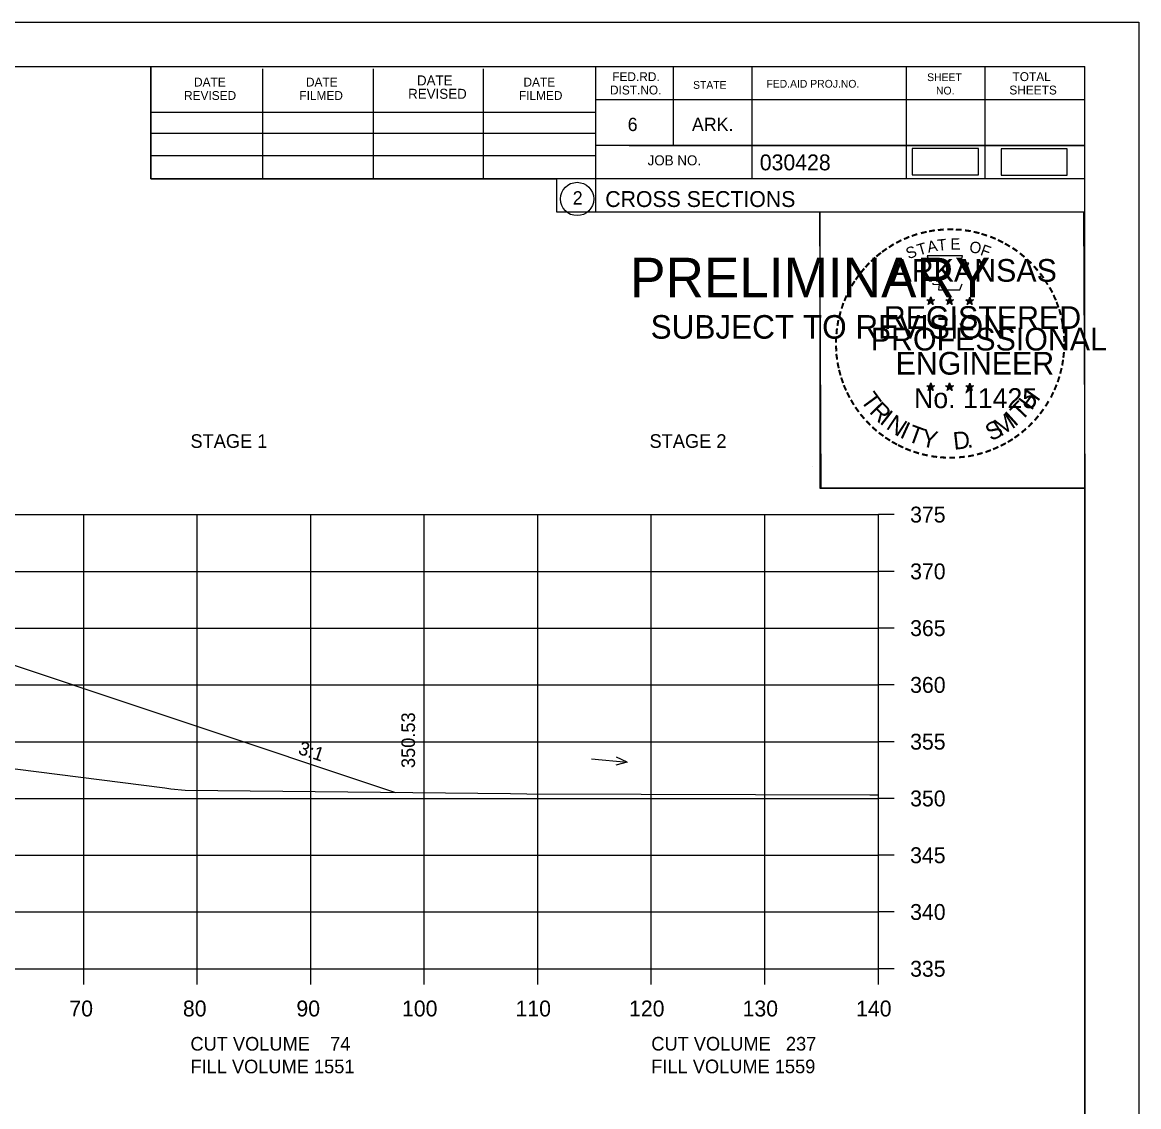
# Model space of a CAD drawing. Extents: x 1374859 to 1376773, y 382242 to 389804.
# Drawn here: x 1376199.2 to 1376297.5, y 384279.6 to 384375.1 of the extents above; entities that cross this region are included whole.
import ezdxf

# ---------------------------------------------------------------- set-up
doc = ezdxf.new("R2010")
doc.units = 0
for name, color, linetype in [('R_Axis', 7, 'Continuous'), ('R_Axis Annot', 7, 'Continuous'), ('R_Border', 7, 'Continuous'), ('R_Border PE', 7, 'Continuous'), ('R_Border Prem', 7, 'Continuous'), ('R_Exist Surface', 7, 'Continuous'), ('R_Fin Surface', 7, 'Continuous'), ('R_Grid', 7, 'Continuous'), ('R_MOT', 7, 'Continuous'), ('R_No Plot', 7, 'Continuous'), ('R_Water Annot', 7, 'Continuous'), ('R_Xsect Elev', 7, 'Continuous'), ('R_Xsect Slope', 7, 'Continuous')]:
    doc.layers.add(name, color=color, linetype=linetype)

msp = doc.modelspace()

# ---------------------------------------------------------------- linework, layer by layer
at = {"layer": 'R_Axis'}
for p, q in [((1376274.57, 384291.762), (1376274.57, 384331.762)), ((1376275.97, 384331.762), (1376274.57, 384331.762)), ((1376275.97, 384326.762), (1376274.57, 384326.762)), ((1376275.97, 384321.762), (1376274.57, 384321.762)), ((1376275.97, 384316.762), (1376274.57, 384316.762)), ((1376275.97, 384311.762), (1376274.57, 384311.762)), ((1376275.97, 384306.762), (1376274.57, 384306.762)), ((1376275.97, 384301.762), (1376274.57, 384301.762)), ((1376275.97, 384296.762), (1376274.57, 384296.762)), ((1375994.57, 384291.762), (1376274.57, 384291.762)), ((1376204.57, 384290.362), (1376204.57, 384291.762)), ((1376214.57, 384290.362), (1376214.57, 384291.762)), ((1376224.57, 384290.362), (1376224.57, 384291.762)), ((1376234.57, 384290.362), (1376234.57, 384291.762)), ((1376244.57, 384290.362), (1376244.57, 384291.762)), ((1376254.57, 384290.362), (1376254.57, 384291.762)), ((1376264.57, 384290.362), (1376264.57, 384291.762)), ((1376274.57, 384290.362), (1376274.57, 384291.762)), ((1376275.97, 384291.762), (1376274.57, 384291.762))]:
    msp.add_line(p, q, dxfattribs=at)
at = {"layer": 'R_Border'}
for p, q in [((1375976.57, 384371.222), (1376292.75, 384371.222)), ((1376210.49, 384361.342), (1376210.49, 384371.222)), ((1376220.35, 384361.342), (1376220.35, 384371.022)), ((1376230.11, 384361.342), (1376230.11, 384371.022)), ((1376239.79, 384361.342), (1376239.79, 384371.022)), ((1376249.65, 384371.222), (1376249.65, 384358.422)), ((1376256.49, 384371.222), (1376256.49, 384364.282)), ((1376263.43, 384371.222), (1376263.43, 384361.342)), ((1376277.01, 384371.222), (1376277.01, 384361.342)), ((1376283.95, 384371.222), (1376283.95, 384361.342)), ((1376292.75, 384165.762), (1376292.75, 384371.222)), ((1376292.75, 384368.282), (1376249.65, 384368.282)), ((1376292.75, 384368.302), (1376292.75, 384368.302)), ((1376210.49, 384367.202), (1376249.65, 384367.202)), ((1376210.49, 384365.342), (1376249.65, 384365.342)), ((1376292.75, 384364.282), (1376249.65, 384364.282)), ((1376252.61, 384364.282), (1376292.75, 384364.282)), ((1376210.49, 384361.342), (1376210.49, 384363.402)), ((1376210.49, 384363.402), (1376249.65, 384363.402)), ((1376292.75, 384361.342), (1376210.49, 384361.342)), ((1376249.65, 384358.422), (1376292.75, 384358.422))]:
    msp.add_line(p, q, dxfattribs=at)
msp.add_circle((1376248.037, 384359.558), 1.467, dxfattribs=at)
at = {"layer": 'R_Border PE'}
for p, q in [((1376278.835, 384350.677), (1376279.184, 384350.566)), ((1376278.835, 384350.677), (1376279.088, 384350.632)), ((1376278.835, 384350.677), (1376279.072, 384350.555)), ((1376278.968, 384350.269), (1376279.184, 384350.566)), ((1376278.968, 384350.269), (1376279.094, 384350.513)), ((1376278.968, 384350.269), (1376279.182, 384350.486)), ((1376279.184, 384350.931), (1376279.143, 384350.679)), ((1376279.397, 384350.269), (1376279.182, 384350.483)), ((1376279.184, 384350.566), (1376279.184, 384350.931)), ((1376279.184, 384350.931), (1376279.233, 384350.681)), ((1376279.531, 384350.677), (1376279.184, 384350.566)), ((1376279.397, 384350.269), (1376279.184, 384350.566)), ((1376279.531, 384350.677), (1376279.245, 384350.628)), ((1376279.397, 384350.269), (1376279.26, 384350.56)), ((1376279.531, 384350.677), (1376279.327, 384350.575)), ((1376280.505, 384350.677), (1376280.854, 384350.566)), ((1376280.505, 384350.677), (1376280.758, 384350.632)), ((1376280.505, 384350.677), (1376280.742, 384350.555)), ((1376280.638, 384350.269), (1376280.854, 384350.566)), ((1376280.638, 384350.269), (1376280.764, 384350.513)), ((1376280.638, 384350.269), (1376280.852, 384350.486)), ((1376280.854, 384350.931), (1376280.813, 384350.679)), ((1376281.067, 384350.269), (1376280.852, 384350.483)), ((1376280.854, 384350.566), (1376280.854, 384350.931)), ((1376280.854, 384350.931), (1376280.903, 384350.681)), ((1376281.201, 384350.677), (1376280.854, 384350.566)), ((1376281.067, 384350.269), (1376280.854, 384350.566)), ((1376281.201, 384350.677), (1376280.915, 384350.628)), ((1376281.067, 384350.269), (1376280.93, 384350.56)), ((1376281.201, 384350.677), (1376280.997, 384350.575)), ((1376282.269, 384350.665), (1376282.618, 384350.554)), ((1376282.269, 384350.665), (1376282.522, 384350.62)), ((1376282.269, 384350.665), (1376282.506, 384350.543)), ((1376282.402, 384350.257), (1376282.618, 384350.554)), ((1376282.402, 384350.257), (1376282.528, 384350.501)), ((1376282.402, 384350.257), (1376282.616, 384350.474)), ((1376282.618, 384350.919), (1376282.577, 384350.667)), ((1376282.831, 384350.257), (1376282.616, 384350.471)), ((1376282.618, 384350.554), (1376282.618, 384350.919)), ((1376282.618, 384350.919), (1376282.667, 384350.669)), ((1376282.965, 384350.665), (1376282.618, 384350.554)), ((1376282.831, 384350.257), (1376282.618, 384350.554)), ((1376282.965, 384350.665), (1376282.679, 384350.616)), ((1376282.831, 384350.257), (1376282.694, 384350.548)), ((1376282.965, 384350.665), (1376282.761, 384350.563)), ((1376279.18, 384343.358), (1376279.139, 384343.106)), ((1376279.18, 384342.993), (1376279.18, 384343.358)), ((1376279.18, 384343.358), (1376279.229, 384343.108)), ((1376280.849, 384343.358), (1376280.808, 384343.106)), ((1376280.849, 384342.993), (1376280.849, 384343.358)), ((1376280.849, 384343.358), (1376280.898, 384343.108)), ((1376282.616, 384343.348), (1376282.575, 384343.096)), ((1376282.616, 384342.983), (1376282.616, 384343.348)), ((1376282.616, 384343.348), (1376282.665, 384343.098)), ((1376278.831, 384343.104), (1376279.18, 384342.993)), ((1376278.831, 384343.104), (1376279.084, 384343.059)), ((1376278.831, 384343.104), (1376279.068, 384342.982)), ((1376278.964, 384342.696), (1376279.18, 384342.993)), ((1376278.964, 384342.696), (1376279.09, 384342.94)), ((1376278.964, 384342.696), (1376279.178, 384342.913)), ((1376279.393, 384342.696), (1376279.178, 384342.91)), ((1376279.527, 384343.104), (1376279.18, 384342.993)), ((1376279.393, 384342.696), (1376279.18, 384342.993)), ((1376279.527, 384343.104), (1376279.241, 384343.055)), ((1376279.393, 384342.696), (1376279.256, 384342.987)), ((1376279.527, 384343.104), (1376279.323, 384343.002)), ((1376280.5, 384343.104), (1376280.849, 384342.993)), ((1376280.5, 384343.104), (1376280.753, 384343.059)), ((1376280.5, 384343.104), (1376280.737, 384342.982)), ((1376280.633, 384342.696), (1376280.849, 384342.993)), ((1376280.633, 384342.696), (1376280.759, 384342.94)), ((1376280.633, 384342.696), (1376280.847, 384342.913)), ((1376281.062, 384342.696), (1376280.847, 384342.91)), ((1376281.196, 384343.104), (1376280.849, 384342.993)), ((1376281.062, 384342.696), (1376280.849, 384342.993)), ((1376281.196, 384343.104), (1376280.91, 384343.055)), ((1376281.062, 384342.696), (1376280.925, 384342.987)), ((1376281.196, 384343.104), (1376280.992, 384343.002)), ((1376282.267, 384343.094), (1376282.616, 384342.983)), ((1376282.267, 384343.094), (1376282.52, 384343.049)), ((1376282.267, 384343.094), (1376282.504, 384342.972)), ((1376282.4, 384342.686), (1376282.616, 384342.983)), ((1376282.4, 384342.686), (1376282.526, 384342.93)), ((1376282.4, 384342.686), (1376282.614, 384342.903)), ((1376282.829, 384342.686), (1376282.614, 384342.9)), ((1376282.963, 384343.094), (1376282.616, 384342.983)), ((1376282.829, 384342.686), (1376282.616, 384342.983)), ((1376282.963, 384343.094), (1376282.677, 384343.045)), ((1376282.829, 384342.686), (1376282.692, 384342.977)), ((1376282.963, 384343.094), (1376282.759, 384342.992))]:
    msp.add_line(p, q, dxfattribs=at)
for points in [[(1376278.876, 384354.555), (1376279.145, 384353.728)], [(1376282.387, 384353.633), (1376282.529, 384353.917), (1376281.844, 384353.893), (1376281.992, 384354.555), (1376278.876, 384354.555)], [(1376279.368, 384352.132), (1376279.368, 384352.045), (1376279.931, 384352.026), (1376279.877, 384351.553), (1376281.747, 384351.553), (1376281.948, 384352.089)], [(1376279.184, 384350.931), (1376279.397, 384350.269), (1376278.835, 384350.677), (1376279.531, 384350.677), (1376278.968, 384350.269), (1376279.184, 384350.931)], [(1376280.854, 384350.931), (1376281.067, 384350.269), (1376280.505, 384350.677), (1376281.201, 384350.677), (1376280.638, 384350.269), (1376280.854, 384350.931)], [(1376282.618, 384350.919), (1376282.831, 384350.257), (1376282.269, 384350.665), (1376282.965, 384350.665), (1376282.402, 384350.257), (1376282.618, 384350.919)], [(1376279.18, 384343.358), (1376279.393, 384342.696), (1376278.831, 384343.104), (1376279.527, 384343.104), (1376278.964, 384342.696), (1376279.18, 384343.358)], [(1376280.849, 384343.358), (1376281.062, 384342.696), (1376280.5, 384343.104), (1376281.196, 384343.104), (1376280.633, 384342.696), (1376280.849, 384343.358)], [(1376282.616, 384343.348), (1376282.829, 384342.686), (1376282.267, 384343.094), (1376282.963, 384343.094), (1376282.4, 384342.686), (1376282.616, 384343.348)]]:
    msp.add_lwpolyline(points, dxfattribs=at)
for centre, radius in [((1376279.183, 384350.565), 0.172), ((1376279.183, 384350.565), 0.145), ((1376279.183, 384350.565), 0.116), ((1376279.183, 384350.565), 0.0991), ((1376279.183, 384350.565), 0.0747), ((1376279.183, 384350.565), 0.0495), ((1376279.183, 384350.565), 0.0296), ((1376280.853, 384350.565), 0.172), ((1376280.853, 384350.565), 0.145), ((1376280.853, 384350.565), 0.116), ((1376280.853, 384350.565), 0.0991), ((1376280.853, 384350.565), 0.0747), ((1376280.853, 384350.565), 0.0495), ((1376280.853, 384350.565), 0.0296), ((1376282.617, 384350.553), 0.172), ((1376282.617, 384350.553), 0.145), ((1376282.617, 384350.553), 0.116), ((1376282.617, 384350.553), 0.0991), ((1376282.617, 384350.553), 0.0747), ((1376282.617, 384350.553), 0.0495), ((1376282.617, 384350.553), 0.0296), ((1376279.179, 384342.992), 0.172), ((1376279.179, 384342.992), 0.145), ((1376279.179, 384342.992), 0.116), ((1376279.179, 384342.992), 0.0991), ((1376279.179, 384342.992), 0.0747), ((1376279.179, 384342.992), 0.0495), ((1376279.179, 384342.992), 0.0296), ((1376280.848, 384342.992), 0.172), ((1376280.848, 384342.992), 0.145), ((1376280.848, 384342.992), 0.116), ((1376280.848, 384342.992), 0.0991), ((1376280.848, 384342.992), 0.0747), ((1376280.848, 384342.992), 0.0495), ((1376280.848, 384342.992), 0.0296), ((1376282.615, 384342.982), 0.172), ((1376282.615, 384342.982), 0.145), ((1376282.615, 384342.982), 0.116), ((1376282.615, 384342.982), 0.0991), ((1376282.615, 384342.982), 0.0747), ((1376282.615, 384342.982), 0.0495), ((1376282.615, 384342.982), 0.0296)]:
    msp.add_circle(centre, radius, dxfattribs=at)
at = {"layer": 'R_Exist Surface'}
msp.add_lwpolyline([(1376194.813, 384309.835), (1376211.721, 384307.685), (1376212.246, 384307.596), (1376213.521, 384307.497), (1376242.163, 384307.184), (1376243.607, 384307.179), (1376273.808, 384307.068), (1376274.57, 384307.085)], dxfattribs=at)
at = {"layer": 'R_Fin Surface'}
msp.add_lwpolyline([(1376042.155, 384308.302), (1376049.774, 384305.762), (1376055.561, 384307.692), (1376059.598, 384309.039), (1376061.685, 384309.733), (1376075.086, 384314.199), (1376082.791, 384315.484), (1376096.748, 384317.81), (1376105.086, 384318.452), (1376134.586, 384320.724), (1376164.086, 384322.995), (1376172.086, 384323.611), (1376185.899, 384321.309), (1376194.086, 384319.944), (1376232.034, 384307.295)], dxfattribs=at)
at = {"layer": 'R_Grid'}
for p, q in [((1375994.57, 384331.762), (1376274.57, 384331.762)), ((1376204.57, 384291.762), (1376204.57, 384331.762)), ((1376214.57, 384291.762), (1376214.57, 384331.762)), ((1376224.57, 384291.762), (1376224.57, 384331.762)), ((1376234.57, 384291.762), (1376234.57, 384331.762)), ((1376244.57, 384291.762), (1376244.57, 384331.762)), ((1376254.57, 384291.762), (1376254.57, 384331.762)), ((1376264.57, 384291.762), (1376264.57, 384331.762)), ((1376274.57, 384291.762), (1376274.57, 384331.762)), ((1375994.57, 384326.762), (1376274.57, 384326.762)), ((1375994.57, 384321.762), (1376274.57, 384321.762)), ((1375994.57, 384316.762), (1376274.57, 384316.762)), ((1375994.57, 384311.762), (1376274.57, 384311.762)), ((1375994.57, 384306.762), (1376274.57, 384306.762)), ((1375994.57, 384301.762), (1376274.57, 384301.762)), ((1375994.57, 384296.762), (1376274.57, 384296.762)), ((1375994.57, 384291.762), (1376274.57, 384291.762))]:
    msp.add_line(p, q, dxfattribs=at)
at = {"layer": 'R_MOT'}
for points in [[(1376277.549, 384361.687), (1376283.382, 384361.687), (1376283.382, 384363.997), (1376277.549, 384363.997)], [(1376285.379, 384361.658), (1376291.213, 384361.658), (1376291.213, 384363.969), (1376285.379, 384363.969)]]:
    msp.add_lwpolyline(points, close=True, dxfattribs=at)
at = {"layer": 'R_No Plot'}
for p, q in [((1375964.17, 384375.117), (1376297.503, 384375.117)), ((1376268.785, 384335.967), (1376268.785, 384335.967))]:
    msp.add_line(p, q, dxfattribs=at)
for points in [[(1375964.163, 384375.117), (1376297.503, 384375.117), (1376297.503, 384161.779), (1375964.163, 384161.779)], [(1376210.49, 384371.222), (1376210.49, 384361.342), (1376246.222, 384361.342), (1376246.222, 384358.422), (1376269.422, 384358.422), (1376269.422, 384334.089), (1376292.75, 384334.089), (1376292.75, 384165.762), (1375976.57, 384165.762), (1375976.57, 384371.222)], [(1376269.422, 384358.422), (1376292.63, 384358.422), (1376292.75, 384334.089), (1376269.543, 384334.089)]]:
    msp.add_lwpolyline(points, close=True, dxfattribs=at)
at = {"layer": 'R_Water Annot'}
for p, q in [((1376249.311, 384310.253), (1376252.438, 384309.946)), ((1376252.438, 384309.946), (1376251.447, 384309.692)), ((1376252.438, 384309.946), (1376251.515, 384310.388))]:
    msp.add_line(p, q, dxfattribs=at)

# ---------------------------------------------------------------- texts
at = {"layer": 'R_Axis Annot'}
for s, p in [('STAGE 1', (1376213.974, 384337.638)), ('STAGE 2', (1376254.415, 384337.64))]:
    msp.add_text(s, height=1.2, rotation=360, dxfattribs=at).set_placement(p)
for s, height, p in [('375', 1.4, (1376277.37, 384331.062)), ('370', 1.4, (1376277.37, 384326.062)), ('365', 1.4, (1376277.37, 384321.062)), ('360', 1.4, (1376277.37, 384316.062)), ('355', 1.4, (1376277.37, 384311.062)), ('350', 1.4, (1376277.37, 384306.062)), ('345', 1.4, (1376277.37, 384301.062)), ('340', 1.4, (1376277.37, 384296.062)), ('335', 1.4, (1376277.37, 384291.062)), ('70', 1.4, (1376203.309, 384287.562)), ('80', 1.4, (1376213.309, 384287.562)), ('90', 1.4, (1376223.309, 384287.562)), ('100', 1.4, (1376232.609, 384287.562)), ('110', 1.4, (1376242.609, 384287.562)), ('120', 1.4, (1376252.609, 384287.562)), ('130', 1.4, (1376262.609, 384287.562)), ('140', 1.4, (1376272.609, 384287.562)), ('CUT VOLUME    74', 1.2, (1376213.974, 384284.555)), ('CUT VOLUME   237', 1.2, (1376254.57, 384284.562)), ('FILL VOLUME 1551', 1.2, (1376213.974, 384282.555)), ('FILL VOLUME 1559', 1.2, (1376254.57, 384282.562))]:
    msp.add_text(s, height=height, dxfattribs=at).set_placement(p)
at = {"layer": 'R_Border'}
for s, height, p in [('DATE', 0.7819, (1376214.29, 384369.462)), ('DATE', 0.7819, (1376224.15, 384369.462)), ('DATE', 0.8792, (1376233.93, 384369.562)), ('DATE', 0.7819, (1376243.31, 384369.462)), ('FED.RD.', 0.7819, (1376251.13, 384369.942)), ('STATE', 0.684, (1376258.25, 384369.262)), ('FED.AID PROJ.NO.', 0.684, (1376264.71, 384369.362)), ('SHEET', 0.684, (1376278.87, 384369.942)), ('TOTAL', 0.7819, (1376286.39, 384369.942)), ('REVISED', 0.7819, (1376213.41, 384368.282)), ('FILMED', 0.7819, (1376223.57, 384368.282)), ('REVISED', 0.8792, (1376233.15, 384368.382)), ('FILMED', 0.7819, (1376242.91, 384368.282)), ('DIST.NO.', 0.7819, (1376250.93, 384368.762)), ('NO.', 0.684, (1376279.65, 384368.762)), ('SHEETS', 0.7819, (1376286.11, 384368.762)), ('6', 1.172, (1376252.49, 384365.542)), ('ARK.', 1.1723, (1376258.15, 384365.542)), ('JOB NO.', 0.8792, (1376254.25, 384362.522)), ('030428', 1.4, (1376264.126, 384362.082)), ('2', 1.172, (1376247.654, 384359.071)), ('CROSS SECTIONS', 1.4, (1376250.514, 384358.852))]:
    msp.add_text(s, height=height, rotation=360, dxfattribs=at).set_placement(p)
at = {"layer": 'R_Border PE'}
for s, height, rotation, p in [('-', 1.6, 24.30721, (1376276.99, 384355.413)), ('-', 1.6, 19.17608, (1376277.624, 384355.682)), ('-', 1.6, 13.63015, (1376278.374, 384355.923)), ('-', 1.6, 10.21935, (1376279.052, 384356.085)), ('T', 1, 6.02276, (1376279.82, 384354.981)), ('-', 1.6, 5.89682, (1376279.781, 384356.195)), ('-', 1.6, 0.18623, (1376280.553, 384356.267)), ('E', 1, 0.83234, (1376280.925, 384355.091)), ('-', 1.6, 357.74304, (1376281.276, 384356.254)), ('-', 1.6, 352.16172, (1376282.02, 384356.198)), ('-', 1.6, 347.20489, (1376282.739, 384356.084)), ('-', 1.6, 342.3362, (1376283.374, 384355.929)), ('-', 1.6, 337.85509, (1376284.109, 384355.706)), ('-', 1.6, 36.23174, (1376275.182, 384354.331)), ('-', 1.6, 34.06357, (1376275.76, 384354.726)), ('-', 1.6, 28.79182, (1376276.357, 384355.096)), ('S', 1, 21.59401, (1376277.231, 384354.233)), ('T', 1, 16.4036, (1376278.145, 384354.564)), ('A', 1, 11.21318, (1376278.971, 384354.815)), ('O', 1, 350.4515, (1376282.529, 384354.881)), ('F', 1, 340.07066, (1376283.483, 384354.653)), ('-', 1.6, 334.12109, (1376284.74, 384355.435)), ('-', 1.6, 329.64089, (1376285.319, 384355.152)), ('-', 1.6, 325.86266, (1376285.962, 384354.791)), ('-', 1.6, 42.96224, (1376274.273, 384353.536)), ('-', 1.6, 38.95066, (1376274.706, 384353.953)), ('ARKANSAS', 2, 360, (1376275.729, 384352.267)), ('-', 1.6, 320.52971, (1376286.572, 384354.365)), ('-', 1.6, 315.57859, (1376287.171, 384353.877)), ('-', 1.6, 50.61417, (1376273.422, 384352.572)), ('-', 1.6, 48.42305, (1376273.825, 384353.058)), ('-', 1.6, 309.87973, (1376287.74, 384353.327)), ('-', 1.6, 58.07063, (1376272.684, 384351.478)), ('-', 1.6, 54.23247, (1376273.009, 384352.005)), ('-', 1.6, 306.65218, (1376288.265, 384352.725)), ('-', 1.4, 303.67529, (1376288.751, 384352.157)), ('-', 1.6, 62.87135, (1376272.371, 384350.864)), ('-', 1.6, 299.66835, (1376289.07, 384351.55)), ('-', 1.6, 294.66279, (1376289.394, 384350.938)), ('-', 1.6, 72.39447, (1376271.893, 384349.623)), ('-', 1.6, 67.77427, (1376272.112, 384350.253)), ('REGISTERED', 2, 360, (1376275.051, 384348.118)), ('DWB', 0.01, 360, (1376279.171, 384350.561)), ('DWB', 0.01, 360, (1376280.841, 384350.561)), ('DWB', 0.01, 360, (1376282.605, 384350.55)), ('-', 1.6, 290.57283, (1376289.651, 384350.361)), ('-', 1.6, 75.46096, (1376271.696, 384348.909)), ('-', 1.6, 285.12326, (1376289.885, 384349.781)), ('-', 1.6, 85.18634, (1376271.488, 384347.505)), ('-', 1.6, 81.20126, (1376271.564, 384348.196)), ('PROFESSIONAL', 2, 360, (1376273.903, 384346.214)), ('-', 1.6, 280.54934, (1376290.085, 384349.039)), ('-', 1.6, 276.59616, (1376290.247, 384348.271)), ('-', 1.6, 89.06224, (1376271.463, 384346.804)), ('-', 1.6, 274.33011, (1376290.307, 384347.549)), ('-', 1.6, 94.19588, (1376271.498, 384346.079)), ('-', 1.6, 269.94067, (1376290.341, 384346.917)), ('-', 1.6, 98.94793, (1376271.57, 384345.412)), ('ENGINEER', 2, 360, (1376276.09, 384344.089)), ('-', 1.6, 260.99529, (1376290.251, 384345.597)), ('-', 1.6, 263.5172, (1376290.322, 384346.251)), ('-', 1.6, 101.71495, (1376271.705, 384344.679)), ('-', 1.6, 105.45785, (1376271.867, 384344.084)), ('-', 1.6, 255.7626, (1376290.141, 384344.919)), ('-', 1.6, 109.08742, (1376272.082, 384343.453)), ('-', 1.6, 252.86809, (1376289.96, 384344.199)), ('-', 1.6, 114.06432, (1376272.336, 384342.857)), ('-', 1.6, 115.72885, (1376272.641, 384342.239)), ('T', 1.54, 306.04056, (1376272.94, 384341.831)), ('No. 11425', 1.757, 360, (1376277.718, 384341.138)), ('DWB', 0.01, 360, (1376279.167, 384342.988)), ('DWB', 0.01, 360, (1376280.836, 384342.988)), ('DWB', 0.01, 360, (1376282.603, 384342.978)), ('H', 1.54, 54.60883, (1376288.06, 384340.866)), ('-', 1.6, 244.61971, (1376289.475, 384342.897)), ('-', 1.6, 247.88866, (1376289.737, 384343.526)), ('-', 1.6, 120.44712, (1376272.998, 384341.653)), ('R', 1.54, 314.00497, (1376273.702, 384340.784)), ('T', 1.54, 46.64442, (1376287.17, 384339.924)), ('-', 1.6, 239.07125, (1376289.081, 384342.145)), ('-', 1.6, 125.89344, (1376273.401, 384341.092)), ('-', 1.6, 130.71812, (1376273.863, 384340.54)), ('I', 1.54, 321.96938, (1376274.603, 384339.852)), ('N', 1.54, 326.50021, (1376275.17, 384339.38)), ('M', 1.54, 32.65632, (1376285.325, 384338.599)), ('I', 1.54, 42.11359, (1376286.609, 384339.446)), ('-', 1.6, 231.25377, (1376288.249, 384340.926)), ('-', 1.6, 233.84524, (1376288.679, 384341.492)), ('-', 1.6, 134.22381, (1376274.38, 384339.995)), ('-', 1.6, 138.93382, (1376274.905, 384339.531)), ('I', 1.54, 335.36034, (1376276.378, 384338.594)), ('T', 1.54, 339.89117, (1376277.039, 384338.267)), ('S', 1.54, 26.9312, (1376284.486, 384338.193)), ('-', 1.6, 221.08509, (1376287.248, 384339.853)), ('-', 1.6, 225.76533, (1376287.77, 384340.362)), ('-', 1.6, 144.64634, (1376275.461, 384339.125)), ('-', 1.6, 148.08978, (1376276.022, 384338.754)), ('Y', 1.54, 347.85558, (1376278.256, 384337.821)), ('D', 1.54, 6.39691, (1376281.241, 384337.463)), ('-', 1.6, 212.24909, (1376286.165, 384338.994)), ('-', 1.6, 215.73633, (1376286.699, 384339.381)), ('-', 1.6, 151.57039, (1376276.601, 384338.429)), ('-', 1.6, 154.60019, (1376277.123, 384338.182)), ('-', 1.6, 158.56121, (1376277.747, 384337.928)), ('-', 1.6, 162.79826, (1376278.434, 384337.715)), ('.', 1.54, 13.76417, (1376282.433, 384337.59)), ('-', 1.6, 200.71842, (1376284.364, 384338.056)), ('-', 1.6, 204.25161, (1376284.983, 384338.329)), ('-', 1.6, 207.35684, (1376285.607, 384338.648)), ('-', 1.6, 167.55551, (1376279.149, 384337.551)), ('-', 1.6, 173.11546, (1376279.921, 384337.441)), ('-', 1.6, 176.51827, (1376280.669, 384337.388)), ('-', 1.6, 181.59176, (1376281.413, 384337.407)), ('-', 1.6, 185.81666, (1376282.222, 384337.483)), ('-', 1.6, 191.28576, (1376282.958, 384337.615)), ('-', 1.6, 195.47429, (1376283.687, 384337.814))]:
    msp.add_text(s, height=height, rotation=rotation, dxfattribs=at).set_placement(p)
at = {"layer": 'R_Border Prem'}
for s, height, p in [('PRELIMINARY', 3.5, (1376252.702, 384350.885)), ('DWB', 0.01, (1376253.448, 384352.734)), ('SUBJECT TO REVISION', 2.07511, (1376254.511, 384347.256))]:
    msp.add_text(s, height=height, rotation=360, dxfattribs=at).set_placement(p)
at = {"layer": 'R_Xsect Elev'}
msp.add_text('350.53', height=1.2, rotation=90, dxfattribs=at).set_placement((1376233.756, 384309.437))
at = {"layer": 'R_Xsect Slope'}
msp.add_text('3:1', height=1.2, rotation=341.56505, dxfattribs=at).set_placement((1376223.383, 384310.705))

doc.saveas('drawing.dxf')
